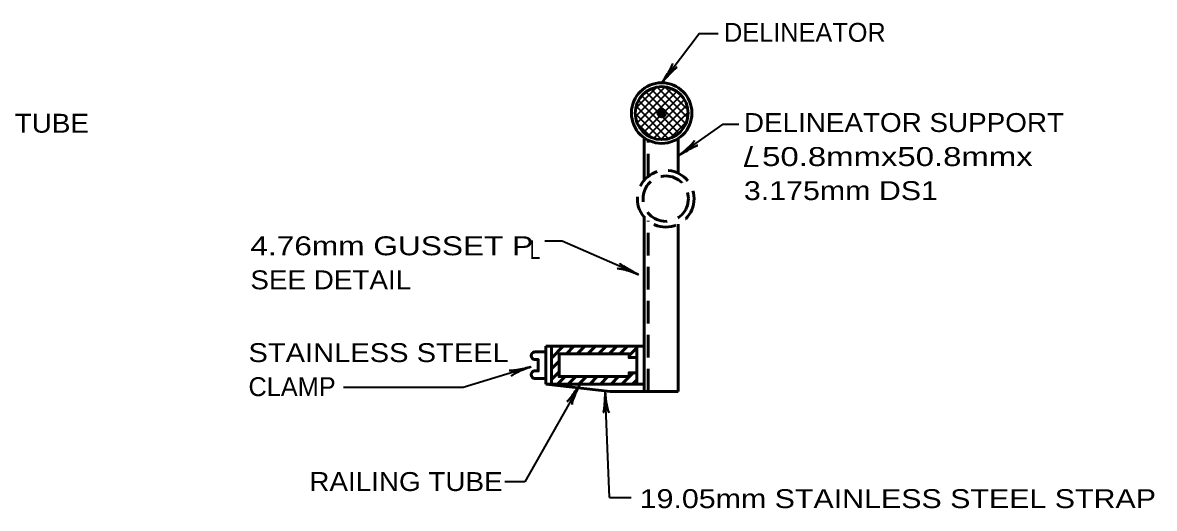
# Model space of a CAD drawing. Extents: x -105 to 751, y -65 to 479.
# Drawn here: x 308.2 to 487.7, y 50.2 to 127.3 of the extents above; entities that cross this region are included whole.
import ezdxf

# ---------------------------------------------------------------- set-up
doc = ezdxf.new("R2010")
doc.units = 0
doc.header["$LTSCALE"] = 1.2
doc.linetypes.add('MEDIUM_DASHED', pattern=[4.5, 3, -1.5])
doc.layers.add('1', color=7, linetype='Continuous', lineweight=35)

msp = doc.modelspace()

# ---------------------------------------------------------------- hatches: boundary and pattern name
at = {"layer": '1'}
msp.add_hatch(color=256, dxfattribs=at).paths.add_polyline_path([(410.151, 112.946, 1), (408.951, 112.946, 1)])

# ---------------------------------------------------------------- linework, layer by layer
for p, q in [((405.388, 112.39), (410.106, 117.108)), ((405.429, 113.704), (408.793, 117.068)), ((405.656, 111.385), (411.113, 116.842)), ((413.379, 111.232), (407.837, 116.773)), ((413.677, 112.206), (408.811, 117.072)), ((413.719, 113.437), (410.042, 117.114)), ((411.539, 109.253), (405.858, 114.934)), ((406.104, 110.561), (411.936, 116.393)), ((412.291, 109.774), (406.38, 115.685)), ((406.694, 109.877), (412.62, 115.803)), ((412.91, 110.428), (407.034, 116.304)), ((407.419, 109.33), (413.167, 115.078)), ((412.576, 115.852), (412.457, 115.972)), ((410.631, 108.888), (405.493, 114.026)), ((408.305, 108.943), (413.554, 114.192)), ((409.391, 108.756), (413.741, 113.106)), ((409.497, 108.75), (405.354, 112.892)), ((407.873, 109.101), (405.705, 111.269)), ((410.878, 108.97), (413.527, 111.619)), ((422.612, 104.565), (424.877, 104.565)), ((396.621, 69.956), (387.842, 54.45)), ((401.272, 51.947), (400.587, 68.85)), ((387.842, 54.45), (384.683, 54.45)), ((401.272, 51.947), (404.695, 51.947))]:
    msp.add_line(p, q, dxfattribs=at)
at = {"layer": '1', "lineweight": 53}
for p, q in [((406.786, 102.311), (406.786, 109.022)), ((412.186, 103.407), (412.186, 108.934)), ((406.786, 68.756), (406.786, 96.433)), ((412.186, 68.756), (412.186, 95.337)), ((391.186, 75.956), (391.186, 69.956)), ((392.086, 75.956), (391.186, 75.956)), ((392.086, 75.789), (392.253, 75.956)), ((392.086, 74.092), (393.95, 75.956)), ((394.447, 74.756), (395.647, 75.956)), ((396.144, 74.756), (397.344, 75.956)), ((397.841, 74.756), (399.041, 75.956)), ((399.538, 74.756), (400.739, 75.956)), ((401.236, 74.756), (402.436, 75.956)), ((402.933, 74.756), (404.133, 75.956)), ((404.386, 74.512), (405.586, 75.712)), ((406.786, 75.956), (405.586, 75.956)), ((392.086, 72.395), (393.286, 73.595)), ((405.586, 71.756), (405.586, 74.156)), ((392.086, 70.698), (393.286, 71.898)), ((393.041, 69.956), (394.241, 71.156)), ((394.739, 69.956), (395.939, 71.156)), ((396.436, 69.956), (397.636, 71.156)), ((398.133, 69.956), (399.333, 71.156)), ((399.83, 69.956), (401.03, 71.156)), ((401.527, 69.956), (402.727, 71.156)), ((403.224, 69.956), (405.024, 71.756)), ((404.921, 69.956), (405.586, 70.621)), ((391.186, 69.956), (401.386, 68.756)), ((392.086, 69.956), (391.186, 69.956)), ((401.386, 68.756), (412.186, 68.756)), ((406.786, 69.956), (405.586, 69.956))]:
    msp.add_line(p, q, dxfattribs=at)
at = {"layer": '1', "linetype": 'MEDIUM_DASHED', "lineweight": 53}
for p, q in [((407.386, 102.888), (407.386, 108.662)), ((407.386, 68.756), (407.386, 95.855))]:
    msp.add_line(p, q, dxfattribs=at)
at = {"layer": '1'}
for points in [[(409.551, 117.746), (415.491, 125.569), (418.519, 125.569)], [(412.186, 106.17), (419.309, 111.213), (421.811, 111.213)], [(405.886, 87.315), (393.767, 92.643), (391.002, 92.643)], [(388.825, 72.684), (378.052, 69.418), (359.083, 69.418)]]:
    msp.add_lwpolyline(points, dxfattribs=at)
at = {"layer": '1', "lineweight": 53}
msp.add_lwpolyline([(392.086, 69.956), (392.086, 75.956), (405.586, 75.956), (405.586, 74.156), (404.386, 74.156), (404.386, 74.756), (393.286, 74.756), (393.286, 71.156), (404.386, 71.156), (404.386, 71.756), (405.586, 71.756), (405.586, 69.956)], close=True, dxfattribs=at)
for points in [[(389.386, 70.856), (391.186, 70.856), (391.186, 75.056), (389.386, 75.056)], [(389.386, 73.856), (389.986, 73.856), (389.986, 72.056), (389.386, 72.056)]]:
    msp.add_lwpolyline(points, dxfattribs=at)
for radius in [4.8, 4.2, 0.6]:
    msp.add_circle((409.551, 112.946), radius, dxfattribs=at)
at = {"layer": '1', "linetype": 'MEDIUM_DASHED', "lineweight": 53}
for radius in [4.5, 3.6]:
    msp.add_circle((410.194, 99.372), radius, dxfattribs=at)
at = {"layer": '1', "lineweight": 53}
for centre in [(389.446, 74.456), (389.446, 71.456)]:
    msp.add_arc(centre, 0.603, 95.72539, 264.27461, dxfattribs=at)
at = {"layer": '1', "lineweight": 40}
for centre, major_axis, ratio, start_param, end_param in [((410.079, 118.989), (-1.147, -1.82), 0.122415, 0.8963533, 3.1415927), ((410.079, 118.989), (-1.147, -1.82), 0.122415, 0.8963533, 3.1415927), ((410.567, 118.663), (1.442, 1.551), 0.07063, 6.2823074, 8.5597026), ((410.567, 118.663), (1.442, 1.551), 0.07063, 6.2823074, 8.5597026), ((413.063, 107.197), (-1.641, -1.391), 0.122415, 0.8963533, 3.1415927), ((413.063, 107.197), (-1.641, -1.391), 0.122415, 0.8963533, 3.1415927), ((413.43, 106.74), (-1.842, -1.046), 0.07063, 3.1407148, 5.41811), ((413.43, 106.74), (-1.842, -1.046), 0.07063, 3.1407148, 5.41811), ((404.554, 87.538), (2.037, -0.691), 0.122415, 0.8963533, 3.1415927), ((404.554, 87.538), (2.037, -0.691), 0.122415, 0.8963533, 3.1415927), ((404.758, 88.088), (1.845, -1.041), 0.07063, 3.1407148, 5.41811), ((404.758, 88.088), (1.845, -1.041), 0.07063, 3.1407148, 5.41811), ((387.464, 72.537), (2.078, 0.41), 0.07063, 3.1407148, 5.41811), ((387.668, 71.987), (1.996, 0.801), 0.122415, 0.8963533, 3.1415927), ((395.737, 68.911), (1.222, 1.73), 0.07063, 3.1407148, 5.41811), ((395.737, 68.911), (1.222, 1.73), 0.07063, 3.1407148, 5.41811), ((396.264, 68.653), (0.893, 1.957), 0.122415, 0.8963533, 3.1415927), ((396.264, 68.653), (0.893, 1.957), 0.122415, 0.8963533, 3.1415927), ((400.387, 67.496), (-0.125, -2.115), 0.07063, 6.2823074, 8.5597026), ((400.971, 67.555), (-0.274, 2.133), 0.122415, 0.8963533, 3.1415927)]:
    msp.add_ellipse(centre, major_axis=major_axis, ratio=ratio, start_param=start_param, end_param=end_param, dxfattribs=at)

# ---------------------------------------------------------------- texts
at = {"layer": '1'}
for s, p in [('DELINEATOR', (419.441, 124.252)), ('CLAMP', (344.029, 68.047))]:
    msp.add_text(s, height=3, dxfattribs=at).set_placement(p)
for s, width, p in [('RAILING TUBE', 1.1, (288.087, 109.833)), ('DELINEATOR SUPPORT', 1.1, (422.588, 109.946)), ('/ 50.8mmx50.8mmx', 1.3, (422.588, 104.546)), ('3.175mm DS1', 1.2, (422.588, 99.146)), ('4.76mm GUSSET P', 1.25, (344.327, 90.391)), ('L', 0.75, (388.624, 89.783)), ('SEE DETAIL', 1.1, (344.327, 84.991)), ('STAINLESS STEEL', 1.15, (344.029, 73.447)), ('RAILING TUBE', 1.1, (353.679, 52.995)), ('19.05mm STAINLESS STEEL STRAP', 1.2, (406.064, 50.282))]:
    msp.add_text(s, height=3, dxfattribs=dict(at, width=width)).set_placement(p)

doc.saveas('drawing.dxf')
